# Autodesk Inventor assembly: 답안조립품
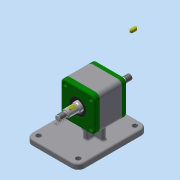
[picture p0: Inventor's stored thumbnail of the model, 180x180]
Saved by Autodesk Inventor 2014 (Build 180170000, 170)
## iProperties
Created: 2020-11
Part Number: 답안조립품
Document SubType Name: Assembly
Designer: kh
Author: kh
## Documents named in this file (7)
- C:\Users\kh\Desktop\701106V1025\답안조립품.iam
- C:\Users\kh\Desktop\701106V1025\본체.ipt
- C:\Users\kh\Desktop\701106V1025\베어링 6004.ipt
- C:\Users\kh\Desktop\701106V1025\축.ipt
- C:\Users\kh\Desktop\701106V1025\커버.ipt
- C:\Users\kh\Desktop\701106V1025\오일 실 17 30 5.ipt
- C:\Users\kh\Desktop\701106V1025\키 5 x 5 x 12.ipt
